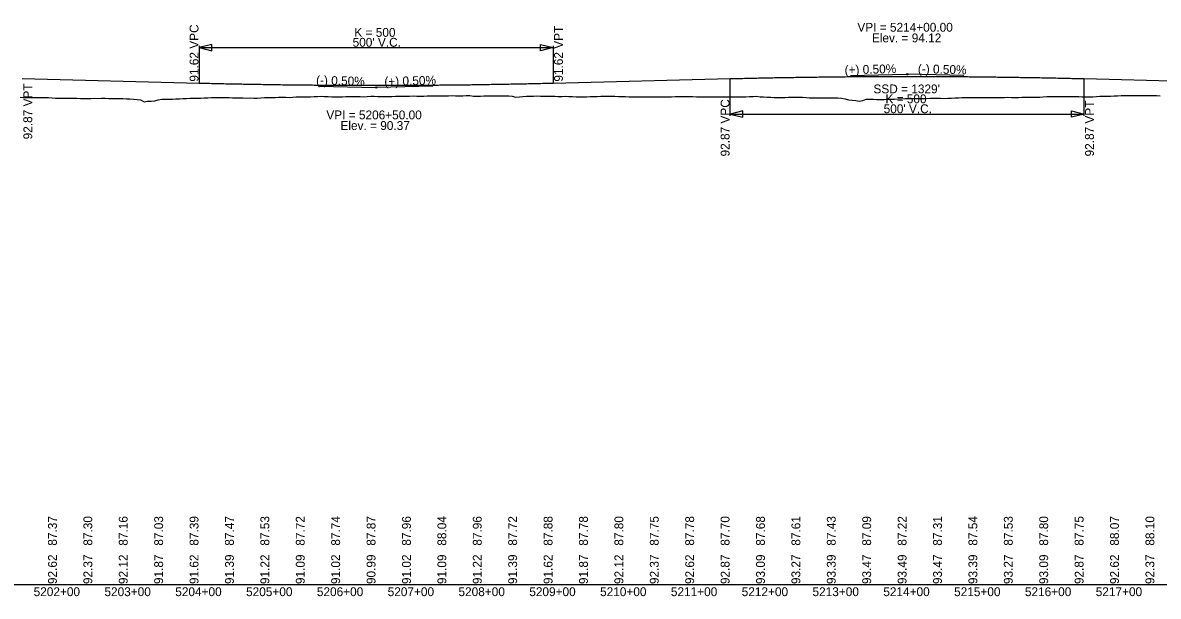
# Model space of a CAD drawing. Extents: x 2147288 to 2220488, y 740833 to 759333.
# Drawn here: x 2152532 to 2154136, y 750067 to 750877 of the extents above; entities that cross this region are included whole.
import ezdxf

# ---------------------------------------------------------------- set-up
doc = ezdxf.new("R2010")
doc.units = 0
for name, color, linetype in [('RD_DDB_GradeTX', 7, 'Continuous'), ('RD_DDB_Profile_EX', 7, 'Continuous'), ('RD_DDB_Profile_Lbl', 7, 'Continuous'), ('RD_DDB_Profile_PR', 7, 'Continuous'), ('RD_DDB_StaTX', 7, 'Continuous'), ('RD_DDB_StripGrade', 7, 'Continuous'), ('RD_DDB_VCLbl', 7, 'Continuous'), ('RD_GPK_Profile_Cell', 7, 'Continuous')]:
    doc.layers.add(name, color=color, linetype=linetype)

msp = doc.modelspace()

# ---------------------------------------------------------------- linework, layer by layer
at = {"layer": 'RD_DDB_GradeTX'}
for p, q in [((2153701.1, 750802), (2153780.1, 750804)), ((2153861.1, 750802), (2153782.1, 750804)), ((2152951.1, 750787.3), (2153030.1, 750785.3)), ((2153111.1, 750787.3), (2153032.1, 750785.3))]:
    msp.add_line(p, q, dxfattribs=at)
for centre in [(2153781.1, 750804), (2153031.1, 750785.3)]:
    msp.add_circle(centre, 1, dxfattribs=at)
at = {"layer": 'RD_DDB_Profile_EX'}
for points in [[(2152528.3, 750771.4), (2152533.3, 750771.3), (2152538.3, 750771.3)], [(2152538.3, 750771.3), (2152543.3, 750771.3), (2152548.3, 750771.2), (2152553.3, 750771.1), (2152558.3, 750771), (2152563.3, 750771), (2152568.3, 750770.9), (2152573.3, 750770.6), (2152578.3, 750770.3), (2152583.3, 750770.2), (2152588.3, 750770.2), (2152593.3, 750770.3), (2152598.3, 750770.2), (2152603.3, 750770.1), (2152608.3, 750770), (2152613.3, 750769.8), (2152618.3, 750769.6), (2152623.3, 750769.7), (2152628.3, 750769.8), (2152633.3, 750770), (2152638.3, 750769.9), (2152643.3, 750770), (2152648.3, 750770), (2152653.3, 750769.8), (2152658.3, 750769.7), (2152663.3, 750769.8), (2152668.3, 750769.7), (2152673.3, 750769.6), (2152678.3, 750769.4), (2152683.3, 750769.1), (2152688.3, 750768.8), (2152693.3, 750768.5), (2152698.3, 750767.8), (2152703.3, 750765.2), (2152708.3, 750765.9), (2152713.3, 750765.8), (2152718.3, 750766.5), (2152723.3, 750767.7), (2152728.3, 750768.6), (2152733.3, 750768.6), (2152738.3, 750768.6), (2152743.3, 750768.9), (2152748.3, 750769.1), (2152753.3, 750769.3), (2152758.3, 750769.7), (2152763.3, 750769.9), (2152768.3, 750770), (2152773.3, 750770.1), (2152778.3, 750770.4), (2152783.3, 750770.4), (2152788.3, 750770.5), (2152793.3, 750770.7), (2152798.3, 750771), (2152803.3, 750771.1), (2152808.3, 750771.2), (2152813.3, 750771.2), (2152818.3, 750771.3), (2152823.3, 750771), (2152828.3, 750770.8), (2152833.3, 750770.7), (2152838.3, 750770.5), (2152843.3, 750770.6), (2152848.3, 750770.3), (2152853.3, 750770.5), (2152858.3, 750770.4), (2152863.3, 750770.4), (2152868.3, 750770.6), (2152873.3, 750770.9), (2152878.3, 750771), (2152883.3, 750771.1), (2152888.3, 750771.3), (2152893.3, 750771.4), (2152898.3, 750771.5), (2152903.3, 750771.4), (2152908.3, 750771.3), (2152913.3, 750771.7), (2152918.3, 750772.1), (2152923.3, 750772.3), (2152928.3, 750772.1), (2152933.3, 750772), (2152938.3, 750772.3), (2152943.3, 750772.5), (2152948.3, 750772.7), (2152953.3, 750772.8), (2152958.3, 750772.6), (2152963.3, 750772.5), (2152968.3, 750772.3), (2152973.3, 750772.3), (2152978.3, 750772.2), (2152983.3, 750772.1), (2152988.3, 750772.5), (2152993.3, 750772.5), (2152998.3, 750772.5), (2153003.3, 750772.5), (2153008.3, 750772.4), (2153013.3, 750772.3), (2153018.3, 750772.4), (2153023.3, 750773), (2153028.3, 750772.9), (2153033.3, 750772.7), (2153038.3, 750772.5)], [(2153038.3, 750772.5), (2153043.3, 750772.5), (2153048.3, 750772.6), (2153053.3, 750772.7), (2153058.3, 750772.8), (2153063.3, 750772.8), (2153068.3, 750772.9), (2153073.3, 750773), (2153078.3, 750773.1), (2153083.3, 750773.3), (2153088.3, 750773.2), (2153093.3, 750772.9), (2153098.3, 750773), (2153103.3, 750773.3), (2153108.3, 750773.4), (2153113.3, 750773.6), (2153118.3, 750773.6), (2153123.3, 750773.4), (2153128.3, 750773.5), (2153133.3, 750773.7), (2153138.3, 750773.8), (2153143.3, 750773.6), (2153148.3, 750773.4), (2153153.3, 750773.5), (2153158.3, 750773.8), (2153163.3, 750773.9), (2153168.3, 750773.1), (2153173.3, 750773.2), (2153178.3, 750773.1), (2153183.3, 750773.3), (2153188.3, 750773.5), (2153193.3, 750773.6), (2153198.3, 750773.6), (2153203.3, 750773.6), (2153208.3, 750773.4), (2153213.3, 750773.3), (2153218.3, 750773.4), (2153223.3, 750773), (2153228.3, 750771.8), (2153233.3, 750772.2), (2153238.3, 750772.7), (2153243.3, 750773.1), (2153248.3, 750773.1), (2153253.3, 750773.1), (2153258.3, 750773.3), (2153263.3, 750773.2), (2153268.3, 750773), (2153273.3, 750772.9), (2153278.3, 750772.9), (2153283.3, 750772.8), (2153288.3, 750772.7), (2153293.3, 750772.6), (2153298.3, 750772.8), (2153303.3, 750772.7), (2153308.3, 750772.7), (2153313.3, 750772.2), (2153318.3, 750771.9), (2153323.3, 750772.2), (2153328.3, 750772.2), (2153333.3, 750772.4), (2153338.3, 750772.6), (2153343.3, 750772.7), (2153348.3, 750772.9), (2153353.3, 750773), (2153358.3, 750773.1), (2153363.3, 750772.9), (2153368.3, 750772.8), (2153373.3, 750772.6), (2153378.3, 750772.5), (2153383.3, 750772.4), (2153388.3, 750772.3), (2153393.3, 750772.3), (2153398.3, 750772.3), (2153403.3, 750772.2), (2153408.3, 750772.2), (2153413.3, 750772.2), (2153418.3, 750772.2), (2153423.3, 750772.2), (2153428.3, 750772.2), (2153433.3, 750772.2), (2153438.3, 750772.2), (2153443.3, 750772.3), (2153448.3, 750772.3), (2153453.3, 750772.4), (2153458.3, 750772.5), (2153463.3, 750772.5), (2153468.3, 750772.6), (2153473.3, 750772.5), (2153478.3, 750772.4), (2153483.3, 750772.3), (2153488.3, 750772.2), (2153493.3, 750772.3), (2153498.3, 750772.2), (2153503.3, 750772.1), (2153508.3, 750772.1), (2153513.3, 750772.1), (2153518.3, 750772), (2153523.3, 750772), (2153528.3, 750771.9), (2153533.3, 750771.9), (2153538.3, 750772)], [(2153538.3, 750772), (2153543.3, 750772.1), (2153548.3, 750772.3), (2153553.3, 750772.3), (2153558.3, 750772.5), (2153563.3, 750772.7), (2153568.3, 750772.8), (2153573.3, 750772.3), (2153578.3, 750772), (2153583.3, 750771.7), (2153588.3, 750771.4), (2153593.3, 750771.1), (2153598.3, 750770.9), (2153603.3, 750771), (2153608.3, 750771.3), (2153613.3, 750771.6), (2153618.3, 750771.8), (2153623.3, 750771.8), (2153628.3, 750771.6), (2153633.3, 750771.4), (2153638.3, 750771.2), (2153643.3, 750770.8), (2153648.3, 750770.8), (2153653.3, 750770.8), (2153658.3, 750770.8), (2153663.3, 750770.8), (2153668.3, 750770.8), (2153673.3, 750770.7), (2153678.3, 750770.6), (2153683.3, 750770.5), (2153688.3, 750770.4), (2153693.3, 750769.2), (2153698.3, 750767.9), (2153703.3, 750767.3), (2153708.3, 750766.7), (2153713.3, 750766), (2153718.3, 750767.1), (2153723.3, 750768.6), (2153728.3, 750769), (2153733.3, 750768.7), (2153738.3, 750768.4), (2153743.3, 750768.3), (2153748.3, 750768.5), (2153753.3, 750768.7), (2153758.3, 750768.8), (2153763.3, 750769), (2153768.3, 750769.3), (2153773.3, 750769.4), (2153778.3, 750769.5), (2153783.3, 750769.6), (2153788.3, 750769.9), (2153793.3, 750769.7), (2153798.3, 750769.6), (2153803.3, 750769.6), (2153808.3, 750769.9), (2153813.3, 750770.3), (2153818.3, 750770.3), (2153823.3, 750770.3), (2153828.3, 750770.1), (2153833.3, 750769.9), (2153838.3, 750770.1), (2153843.3, 750770.3), (2153848.3, 750770.6), (2153853.3, 750770.8), (2153858.3, 750770.9), (2153863.3, 750771), (2153868.3, 750771.1), (2153873.3, 750771.1), (2153878.3, 750771.1), (2153883.3, 750771.1), (2153888.3, 750771.2), (2153893.3, 750771.2), (2153898.3, 750771.2), (2153903.3, 750771.2), (2153908.3, 750771.2), (2153913.3, 750771.1), (2153918.3, 750771.3), (2153923.3, 750771.4), (2153928.3, 750771), (2153933.3, 750771.2), (2153938.3, 750771.3), (2153943.3, 750771.4), (2153948.3, 750771.8), (2153953.3, 750771.8), (2153958.3, 750771.5), (2153963.3, 750771.7), (2153968.3, 750771.8), (2153973.3, 750772.1), (2153978.3, 750772.4), (2153983.3, 750772.4), (2153988.3, 750772.4), (2153993.3, 750772.6), (2153998.3, 750772.7), (2154003.3, 750772.7), (2154008.3, 750772.4), (2154013.3, 750772.4), (2154018.3, 750772.4), (2154023.3, 750772.5), (2154028.3, 750772.2), (2154033.3, 750772.2), (2154038.3, 750772.3)], [(2154038.3, 750772.3), (2154043.3, 750772), (2154048.3, 750772.5), (2154053.3, 750773.2), (2154058.3, 750773), (2154063.3, 750772.8), (2154068.3, 750773.2), (2154073.3, 750773.5), (2154078.3, 750773.6), (2154083.3, 750773.8), (2154088.3, 750774), (2154093.3, 750773.9), (2154098.3, 750773.9), (2154103.3, 750773.9), (2154108.3, 750773.9), (2154113.3, 750773.9), (2154118.3, 750774), (2154123.3, 750774), (2154128.3, 750774), (2154133.3, 750773.9), (2154138.3, 750773.7)]]:
    msp.add_lwpolyline(points, dxfattribs=at)
at = {"layer": 'RD_DDB_Profile_PR'}
for p, q in [((2152531.1, 750797.8), (2152781.1, 750791.5)), ((2153281.1, 750791.5), (2153531.1, 750797.8)), ((2154031.1, 750797.8), (2154231.1, 750792.8))]:
    msp.add_line(p, q, dxfattribs=at)
for points in [[(2153531.1, 750797.8), (2153541.1, 750798), (2153551.1, 750798.2), (2153561.1, 750798.5), (2153571.1, 750798.7), (2153581.1, 750798.9), (2153591.1, 750799.1), (2153601.1, 750799.3), (2153611.1, 750799.4), (2153621.1, 750799.6), (2153631.1, 750799.8), (2153641.1, 750799.9), (2153651.1, 750800), (2153661.1, 750800.2), (2153671.1, 750800.3), (2153681.1, 750800.4), (2153691.1, 750800.5), (2153701.1, 750800.6), (2153711.1, 750800.6), (2153721.1, 750800.7), (2153731.1, 750800.8), (2153741.1, 750800.8), (2153751.1, 750800.8), (2153761.1, 750800.9), (2153771.1, 750800.9), (2153781.1, 750800.9), (2153791.1, 750800.9), (2153801.1, 750800.9), (2153811.1, 750800.8), (2153821.1, 750800.8), (2153831.1, 750800.8), (2153841.1, 750800.7), (2153851.1, 750800.6), (2153861.1, 750800.6), (2153871.1, 750800.5), (2153881.1, 750800.4), (2153891.1, 750800.3), (2153901.1, 750800.2), (2153911.1, 750800), (2153921.1, 750799.9), (2153931.1, 750799.8), (2153941.1, 750799.6), (2153951.1, 750799.4), (2153961.1, 750799.3), (2153971.1, 750799.1), (2153981.1, 750798.9), (2153991.1, 750798.7), (2154001.1, 750798.5), (2154011.1, 750798.2), (2154021.1, 750798), (2154031.1, 750797.8)], [(2152781.1, 750791.5), (2152791.1, 750791.3), (2152801.1, 750791), (2152811.1, 750790.8), (2152821.1, 750790.6), (2152831.1, 750790.4), (2152841.1, 750790.2), (2152851.1, 750790), (2152861.1, 750789.8), (2152871.1, 750789.7), (2152881.1, 750789.5), (2152891.1, 750789.4), (2152901.1, 750789.2), (2152911.1, 750789.1), (2152921.1, 750789), (2152931.1, 750788.9), (2152941.1, 750788.8), (2152951.1, 750788.7), (2152961.1, 750788.6), (2152971.1, 750788.6), (2152981.1, 750788.5), (2152991.1, 750788.5), (2153001.1, 750788.4), (2153011.1, 750788.4), (2153021.1, 750788.4), (2153031.1, 750788.4), (2153041.1, 750788.4), (2153051.1, 750788.4), (2153061.1, 750788.4), (2153071.1, 750788.5), (2153081.1, 750788.5), (2153091.1, 750788.6), (2153101.1, 750788.6), (2153111.1, 750788.7), (2153121.1, 750788.8), (2153131.1, 750788.9), (2153141.1, 750789), (2153151.1, 750789.1), (2153161.1, 750789.2), (2153171.1, 750789.4), (2153181.1, 750789.5), (2153191.1, 750789.7), (2153201.1, 750789.8), (2153211.1, 750790), (2153221.1, 750790.2), (2153231.1, 750790.4), (2153241.1, 750790.6), (2153251.1, 750790.8), (2153261.1, 750791), (2153271.1, 750791.3), (2153281.1, 750791.5)]]:
    msp.add_spline(points, degree=3, dxfattribs=at)
at = {"layer": 'RD_DDB_VCLbl'}
for p, q in [((2152781.1, 750844), (2152781.1, 750791.5)), ((2152781.1, 750841.5), (2153281.1, 750841.5)), ((2153281.1, 750844), (2153281.1, 750791.5)), ((2153531.1, 750745.3), (2153531.1, 750797.8)), ((2154031.1, 750745.3), (2154031.1, 750797.8)), ((2153531.1, 750747.8), (2154031.1, 750747.8))]:
    msp.add_line(p, q, dxfattribs=at)
for points in [[(2152799.1, 750846), (2152781.1, 750841.5), (2152799.1, 750837)], [(2153263.1, 750846), (2153281.1, 750841.5), (2153263.1, 750837)], [(2153549.1, 750752.3), (2153531.1, 750747.8), (2153549.1, 750743.3)], [(2154013.1, 750752.3), (2154031.1, 750747.8), (2154013.1, 750743.3)]]:
    msp.add_lwpolyline(points, close=True, dxfattribs=at)
at = {"layer": 'RD_GPK_Profile_Cell'}
msp.add_line((2148888.3, 750083.4), (2170488.3, 750083.4), dxfattribs=at)

# ---------------------------------------------------------------- texts
at = {"layer": 'RD_DDB_GradeTX'}
for s, rotation, p in [('(+) 0.50%', 1.4321, (2153692.8, 750803.8)), ('(-) 0.50%', 358.5679, (2153796, 750805.6)), ('(-) 0.50%', 358.5679, (2152946.1, 750789.4)), ('(+) 0.50%', 1.4321, (2153042.8, 750787.6))]:
    msp.add_text(s, height=12.5, rotation=rotation, dxfattribs=at).set_placement(p)
at = {"layer": 'RD_DDB_Profile_Lbl'}
for s, p in [('VPI = 5214+00.00', (2153710.7, 750864)), ('Elev. = 94.12', (2153731.2, 750849)), ('VPI = 5206+50.00', (2152960.7, 750740.3)), ('Elev. = 90.37', (2152980.6, 750725.3))]:
    msp.add_text(s, height=12.5, dxfattribs=at).set_placement(p)
at = {"layer": 'RD_DDB_StaTX'}
for s, p in [('5202+00', (2152547.3, 750067.2)), ('5203+00', (2152647.3, 750067.2)), ('5204+00', (2152747.3, 750067.2)), ('5205+00', (2152847.3, 750067.2)), ('5206+00', (2152947.3, 750067.2)), ('5207+00', (2153047.3, 750067.2)), ('5208+00', (2153147.3, 750067.2)), ('5209+00', (2153247.3, 750067.2)), ('5210+00', (2153347.3, 750067.2)), ('5211+00', (2153447.3, 750067.2)), ('5212+00', (2153547.3, 750067.2)), ('5213+00', (2153647.3, 750067.2)), ('5214+00', (2153747.3, 750067.2)), ('5215+00', (2153847.3, 750067.2)), ('5216+00', (2153947.3, 750067.2)), ('5217+00', (2154047.3, 750067.2))]:
    msp.add_text(s, height=12.5, dxfattribs=at).set_placement(p)
at = {"layer": 'RD_DDB_StripGrade'}
for s, p in [('91.62 VPC', (2152780.1, 750793.5)), ('91.62 VPT', (2153294.8, 750793.5)), ('92.87 VPT', (2152545.3, 750712)), ('92.87 VPC', (2153530.1, 750687.9)), ('92.87 VPT', (2154044.8, 750687.9)), ('87.37', (2152580.1, 750138.4)), ('87.30', (2152630.1, 750138.4)), ('87.16', (2152680.1, 750138.4)), ('87.03', (2152730.1, 750138.4)), ('87.39', (2152780.1, 750138.4)), ('87.47', (2152830.1, 750138.4)), ('87.53', (2152880.1, 750138.4)), ('87.72', (2152930.1, 750138.4)), ('87.74', (2152980.1, 750138.4)), ('87.87', (2153030.1, 750138.4)), ('87.96', (2153080.1, 750138.4)), ('88.04', (2153130.1, 750138.4)), ('87.96', (2153180.1, 750138.4)), ('87.72', (2153230.1, 750138.4)), ('87.88', (2153280.1, 750138.4)), ('87.78', (2153330.1, 750138.4)), ('87.80', (2153380.1, 750138.4)), ('87.75', (2153430.1, 750138.4)), ('87.78', (2153480.1, 750138.4)), ('87.70', (2153530.1, 750138.4)), ('87.68', (2153580.1, 750138.4)), ('87.61', (2153630.1, 750138.4)), ('87.43', (2153680.1, 750138.4)), ('87.09', (2153730.1, 750138.4)), ('87.22', (2153780.1, 750138.4)), ('87.31', (2153830.1, 750138.4)), ('87.54', (2153880.1, 750138.4)), ('87.53', (2153930.1, 750138.4)), ('87.80', (2153980.1, 750138.4)), ('87.75', (2154030.1, 750138.4)), ('88.07', (2154080.1, 750138.4)), ('88.10', (2154130.1, 750138.4)), ('92.62', (2152580.1, 750084.2)), ('92.37', (2152630.1, 750084.2)), ('92.12', (2152680.1, 750084.2)), ('91.87', (2152730.1, 750084.2)), ('91.62', (2152780.1, 750084.2)), ('91.39', (2152830.1, 750084.2)), ('91.22', (2152880.1, 750084.2)), ('91.09', (2152930.1, 750084.2)), ('91.02', (2152980.1, 750084.2)), ('90.99', (2153030.1, 750084.2)), ('91.02', (2153080.1, 750084.2)), ('91.09', (2153130.1, 750084.2)), ('91.22', (2153180.1, 750084.2)), ('91.39', (2153230.1, 750084.2)), ('91.62', (2153280.1, 750084.2)), ('91.87', (2153330.1, 750084.2)), ('92.12', (2153380.1, 750084.2)), ('92.37', (2153430.1, 750084.2)), ('92.62', (2153480.1, 750084.2)), ('92.87', (2153530.1, 750084.2)), ('93.09', (2153580.1, 750084.2)), ('93.27', (2153630.1, 750084.2)), ('93.39', (2153680.1, 750084.2)), ('93.47', (2153730.1, 750084.2)), ('93.49', (2153780.1, 750084.2)), ('93.47', (2153830.1, 750084.2)), ('93.39', (2153880.1, 750084.2)), ('93.27', (2153930.1, 750084.2)), ('93.09', (2153980.1, 750084.2)), ('92.87', (2154030.1, 750084.2)), ('92.62', (2154080.1, 750084.2)), ('92.37', (2154130.1, 750084.2))]:
    msp.add_text(s, height=12.5, rotation=90, dxfattribs=at).set_placement(p)
at = {"layer": 'RD_DDB_VCLbl'}
for s, p in [('K = 500', (2153000.3, 750856.8)), ("500' V.C.", (2152997.8, 750842.8)), ("SSD = 1329'", (2153733.4, 750777)), ("500' V.C.", (2153747.8, 750749)), ('K = 500', (2153750.3, 750763))]:
    msp.add_text(s, height=12.5, dxfattribs=at).set_placement(p)

doc.saveas('drawing.dxf')
